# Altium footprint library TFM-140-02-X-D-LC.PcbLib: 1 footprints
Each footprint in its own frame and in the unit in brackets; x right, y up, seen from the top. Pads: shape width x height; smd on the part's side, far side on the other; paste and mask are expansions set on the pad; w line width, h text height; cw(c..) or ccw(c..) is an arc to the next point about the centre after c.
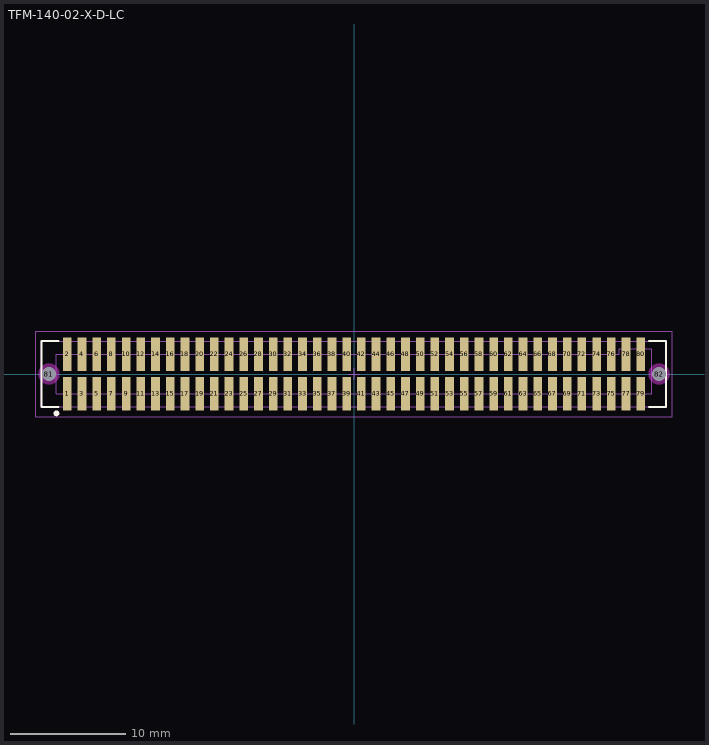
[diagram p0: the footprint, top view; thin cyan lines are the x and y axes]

## TFM-140-02-X-D-LC [mm] "1.27mm pitch, 80 pin, terminal strip; w/locking clips, SMT"
height 5.72
pads (82):
  rect 0.75x2.9 smd mask+0: 1(-24.765,-1.714) 2(-24.765,1.714) 3(-23.495,-1.714) 4(-23.495,1.714) 5(-22.225,-1.714) 6(-22.225,1.714) 7(-20.955,-1.714) 8(-20.955,1.714) 9(-19.685,-1.714) 10(-19.685,1.714) 11(-18.415,-1.714) 12(-18.415,1.714) 13(-17.145,-1.714) 14(-17.145,1.714) 15(-15.875,-1.714) 16(-15.875,1.714) 17(-14.605,-1.714) 18(-14.605,1.714) 19(-13.335,-1.714) 20(-13.335,1.714) 21(-12.065,-1.714) 22(-12.065,1.714) 23(-10.795,-1.714) 24(-10.795,1.714) 25(-9.525,-1.714) 26(-9.525,1.714) 27(-8.255,-1.714) 28(-8.255,1.714) 29(-6.985,-1.714) 30(-6.985,1.714) 31(-5.715,-1.714) 32(-5.715,1.714) 33(-4.445,-1.714) 34(-4.445,1.714) 35(-3.175,-1.714) 36(-3.175,1.714) 37(-1.905,-1.714) 38(-1.905,1.714) 39(-0.635,-1.714) 40(-0.635,1.714) 41(0.635,-1.714) 42(0.635,1.714) 43(1.905,-1.714) 44(1.905,1.714) 45(3.175,-1.714) 46(3.175,1.714) 47(4.445,-1.714) 48(4.445,1.714) 49(5.715,-1.714) 50(5.715,1.714) 51(6.985,-1.714) 52(6.985,1.714) 53(8.255,-1.714) 54(8.255,1.714) 55(9.525,-1.714) 56(9.525,1.714) 57(10.795,-1.714) 58(10.795,1.714) 59(12.065,-1.714) 60(12.065,1.714) 61(13.335,-1.714) 62(13.335,1.714) 63(14.605,-1.714) 64(14.605,1.714) 65(15.875,-1.714) 66(15.875,1.714) 67(17.145,-1.714) 68(17.145,1.714) 69(18.415,-1.714) 70(18.415,1.714) 71(19.685,-1.714) 72(19.685,1.714) 73(20.955,-1.714) 74(20.955,1.714) 75(22.225,-1.714) 76(22.225,1.714) 77(23.495,-1.714) 78(23.495,1.714) 79(24.765,-1.714) 80(24.765,1.714)
  round 1 hole 1.2 unplated mask+0: 81(-26.352,0) 82(26.352,0)
Top Overlay:
  circle w0.25: c-25.7,-3.4 r0.125
  lines w0.2: -25.55,-2.85 -27,-2.85 -27,2.85 -25.55,2.85 ; 25.5,-2.85 26.95,-2.85 26.95,2.85 25.5,2.85
Keep-Out Layer:
  pour cut-out: 27.26,0 27.23,0.235 27.139,0.454 26.995,0.642 26.807,0.786 26.588,0.877 26.353,0.908 26.118,0.877 25.899,0.786 25.711,0.642 25.567,0.454 25.476,0.235 25.445,0 25.476,-0.235 25.567,-0.454 25.711,-0.642 25.899,-0.786 26.118,-0.877 26.353,-0.908 26.588,-0.877 26.807,-0.786 26.995,-0.642 27.139,-0.454 27.23,-0.235
  pour cut-out: -25.445,0 -25.476,0.235 -25.567,0.454 -25.711,0.642 -25.899,0.786 -26.118,0.877 -26.353,0.908 -26.588,0.877 -26.807,0.786 -26.995,0.642 -27.139,0.454 -27.23,0.235 -27.26,0 -27.23,-0.235 -27.139,-0.454 -26.995,-0.642 -26.807,-0.786 -26.588,-0.877 -26.353,-0.908 -26.118,-0.877 -25.899,-0.786 -25.711,-0.642 -25.567,-0.454 -25.476,-0.235
Mechanical 12:
  lines w0.001: -27,-2.85 -27,2.85 26.95,2.85 26.95,-2.85 -27,-2.85 ; -25.7,-1.7 -25.7,1.7 22.9,1.7 22.9,2.2 25.7,2.2 25.7,-1.7 -25.7,-1.7
Mechanical 13:
  circle w0.1: c-25.685,-3.381 r0.127
  lines w0.1: -27,-2.85 -27,2.85 26.95,2.85 26.95,-2.85 -27,-2.85 ; -25.7,-1.7 -25.7,1.7 22.9,1.7 22.9,2.2 25.7,2.2 25.7,-1.7 -25.7,-1.7
  text ".Designator" at 0,-0.127 h1.52
Mechanical 15:
  lines w0.05: -0.5,0 0.5,0 ; 0,-0.5 0,0.5 ; -27.483,-3.683 -27.483,3.683 27.483,3.683 27.483,-3.683 -27.483,-3.683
